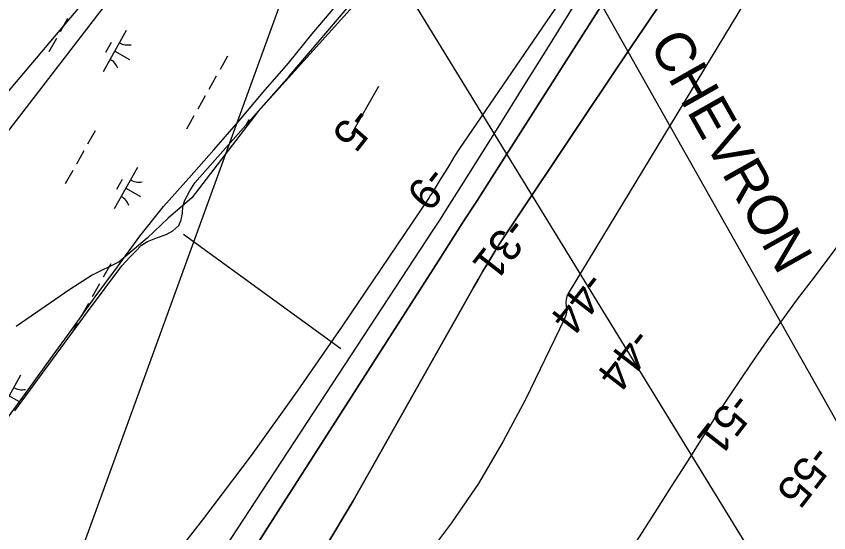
# Model space of a CAD drawing. Extents: x 3913936 to 3933962, y 195330 to 217741.
# Drawn here: x 3922950 to 3923806, y 202729 to 203273 of the extents above; entities that cross this region are included whole.
import ezdxf

# ---------------------------------------------------------------- set-up
doc = ezdxf.new("R2010")
doc.units = 0
for name, color, linetype in [('V-ANNO-TEXT', 7, 'Continuous'), ('V-LEVE-TOET', 7, 'Continuous'), ('V-RIVR-EDGE', 7, 'Continuous'), ('V-RIVR-RANG', 7, 'Continuous'), ('V-RRAP-FSHR', 7, 'Continuous'), ('V-TOPO-DPTH', 7, 'Continuous'), ('V-TOPO-MAJR', 7, 'Continuous'), ('V-TOPO-MINR', 7, 'Continuous'), ('V-UTIL-IDEN', 7, 'Continuous'), ('V-UTIL-LINE', 7, 'Continuous'), ('V-WETL-SWMP', 7, 'Continuous')]:
    doc.layers.add(name, color=color, linetype=linetype)

msp = doc.modelspace()

# ---------------------------------------------------------------- linework, layer by layer
at = {"layer": 'V-ANNO-TEXT'}
msp.add_lwpolyline([(3923713.15, 204620.63), (3922595.25, 201547.11)], dxfattribs=at)
at = {"layer": 'V-LEVE-TOET'}
msp.add_line((3923126.26, 203043.7), (3923292.08, 202923.2), dxfattribs=at)
at = {"layer": 'V-RIVR-EDGE'}
msp.add_lwpolyline([(3923321.17, 203302.44), (3923204.48, 203172.78), (3923134.93, 203082.02), (3923110.18, 203060.8), (3923087.78, 203039.58), (3923058.32, 203014.83), (3923030.03, 203000.69), (3923006.45, 202985.36), (3922949.87, 202946.46)], dxfattribs=at)
at = {"layer": 'V-RRAP-FSHR'}
msp.add_lwpolyline([(3922939.13, 202847.62), (3922962.63, 202879.98), (3922986.14, 202912.35), (3923009.65, 202944.71), (3923033.16, 202977.72), (3923056.66, 203009.43), (3923080.17, 203041.8), (3923105.14, 203072.99), (3923131.68, 203102.91), (3923158.23, 203132.83), (3923184.52, 203162.97), (3923210.3, 203193.56), (3923236.77, 203224.14), (3923261.86, 203254.73), (3923287.64, 203285.31)], dxfattribs=at)
at = {"layer": 'V-TOPO-DPTH'}
for points in [[(3924399.57, 204415.69), (3923953.85, 203655.86), (3923952.77, 203654.08), (3923950.87, 203651.18), (3923886.24, 203555.82), (3923853.92, 203507.32), (3923822.1, 203458.5), (3923791.04, 203409.19), (3923760.48, 203359.56), (3923531.63, 202981.34), (3923530.2, 202978.21), (3923529.27, 202974.99), (3923529.1, 202971.64), (3923529.42, 202968.21), (3923529.81, 202964.75), (3923529.74, 202961.35), (3923528.99, 202958.03), (3923527.8, 202954.76), (3923486.42, 202869.69), (3923462.69, 202824.86), (3923437.03, 202781.27), (3923408.46, 202739.52), (3923377.96, 202699)], [(3924399.57, 204415.69), (3923953.85, 203655.86), (3923952.77, 203654.08), (3923950.87, 203651.18), (3923886.24, 203555.82), (3923853.92, 203507.32), (3923822.1, 203458.5), (3923791.04, 203409.19), (3923760.48, 203359.56), (3923531.63, 202981.34), (3923530.2, 202978.21), (3923529.27, 202974.99), (3923529.1, 202971.64), (3923529.42, 202968.21), (3923529.81, 202964.75), (3923529.74, 202961.35), (3923528.99, 202958.03), (3923527.8, 202954.76), (3923486.42, 202869.69), (3923462.69, 202824.86), (3923437.03, 202781.27), (3923408.46, 202739.52), (3923377.96, 202699)], [(3923857.86, 203782.03), (3923855.37, 203777.58), (3923834.62, 203742.37), (3923834.22, 203741.94), (3923833.77, 203741.64), (3923832.65, 203741.59), (3923416.84, 203134.08), (3923411.85, 203125.86), (3923406.85, 203117.65), (3923401.82, 203109.45), (3923396.77, 203101.27), (3923389.59, 203089.64), (3923388.11, 203087.28), (3923386.62, 203084.94), (3923385.09, 203082.61), (3923383.55, 203080.3), (3923293.38, 202946.75), (3923245.92, 202878.27), (3923197.37, 202810.59), (3923147.19, 202744.12), (3923095.91, 202678.46), (3922791.11, 202297.8)], [(3922202.27, 201498.77), (3922970.95, 202357.51), (3923063.96, 202493.59), (3923089.04, 202534.05), (3923130.72, 202600.96), (3923172.59, 202667.75), (3923214.77, 202734.34), (3923257.14, 202800.82), (3923394.77, 203015.67), (3923408.23, 203036.69), (3923421.68, 203057.72), (3923435.11, 203078.75), (3923448.54, 203099.79), (3923524.43, 203218.78), (3923575.77, 203299.34), (3923627.08, 203379.91), (3923678.32, 203460.53), (3923729.53, 203541.17), (3923871.35, 203718.33), (3923873.24, 203720.48), (3923889.48, 203748.05)], [(3922202.27, 201498.77), (3922970.95, 202357.51), (3923063.96, 202493.59), (3923089.04, 202534.05), (3923130.72, 202600.96), (3923172.59, 202667.75), (3923214.77, 202734.34), (3923257.14, 202800.82), (3923394.77, 203015.67), (3923408.23, 203036.69), (3923421.68, 203057.72), (3923435.11, 203078.75), (3923448.54, 203099.79), (3923524.43, 203218.78), (3923575.77, 203299.34), (3923627.08, 203379.91), (3923678.32, 203460.53), (3923729.53, 203541.17), (3923871.35, 203718.33), (3923873.24, 203720.48), (3923889.48, 203748.05), (3923909.75, 203692.04)], [(3923909.75, 203692.04), (3923908.53, 203689.99), (3923907.28, 203687.96), (3923904.67, 203683.97), (3923901.98, 203680.03), (3923900.63, 203678.06), (3923899.26, 203676.11), (3923741.31, 203450.39), (3923693.08, 203380.95), (3923645.18, 203311.28), (3923597.79, 203241.27), (3923550.72, 203171.04), (3923460, 203034.62), (3923458.56, 203032.41), (3923457.13, 203030.2), (3923455.73, 203027.96), (3923454.35, 203025.72), (3923446.77, 203013.22), (3923441.66, 203004.69), (3923436.6, 202996.14), (3923431.62, 202987.53), (3923426.69, 202978.9), (3923304.88, 202762.93), (3923245.38, 202663.04)], [(3923245.38, 202663.04), (3923304.88, 202762.93), (3923426.69, 202978.9), (3923431.62, 202987.53), (3923436.6, 202996.14), (3923441.66, 203004.69), (3923446.77, 203013.22), (3923454.35, 203025.72), (3923455.73, 203027.96), (3923457.13, 203030.2), (3923458.56, 203032.41), (3923460, 203034.62), (3923550.72, 203171.04), (3923597.79, 203241.27), (3923645.18, 203311.28), (3923693.08, 203380.95), (3923741.31, 203450.39), (3923899.26, 203676.11)]]:
    msp.add_lwpolyline(points, dxfattribs=at)
at = {"layer": 'V-TOPO-MAJR'}
msp.add_lwpolyline([(3923814.5, 203030.35), (3923790.54, 202998.64), (3923772.87, 202975.25), (3923757.93, 202955.1), (3923743.22, 202934.79), (3923728.85, 202914.23), (3923714.72, 202893.51), (3923687.34, 202852.63), (3923685.77, 202850.17), (3923685.52, 202849.75), (3923685.26, 202849.34), (3923655.33, 202802.01), (3923640.07, 202777.95), (3923624.77, 202753.92), (3923609.4, 202729.94), (3923593.98, 202705.98)], dxfattribs=at)
at = {"layer": 'V-TOPO-MINR'}
for points in [[(3924399.57, 204415.69), (3923953.85, 203655.86), (3923952.77, 203654.08), (3923950.87, 203651.18), (3923886.24, 203555.82), (3923853.92, 203507.32), (3923822.1, 203458.5), (3923791.04, 203409.19), (3923760.48, 203359.56), (3923531.63, 202981.34), (3923530.2, 202978.21), (3923529.27, 202974.99), (3923529.1, 202971.64), (3923529.42, 202968.21), (3923529.81, 202964.75), (3923529.74, 202961.35), (3923528.99, 202958.03), (3923527.8, 202954.76), (3923486.42, 202869.69), (3923462.69, 202824.86), (3923437.03, 202781.27), (3923408.46, 202739.52), (3923377.96, 202699)], [(3923857.86, 203782.03), (3923855.37, 203777.58), (3923834.62, 203742.37), (3923834.22, 203741.94), (3923833.77, 203741.64), (3923832.65, 203741.59), (3923416.84, 203134.08), (3923411.85, 203125.86), (3923406.85, 203117.65), (3923401.82, 203109.45), (3923396.77, 203101.27), (3923389.59, 203089.64), (3923388.11, 203087.28), (3923386.62, 203084.94), (3923385.09, 203082.61), (3923383.55, 203080.3), (3923293.38, 202946.75), (3923245.92, 202878.27), (3923197.37, 202810.59), (3923147.19, 202744.12), (3923095.91, 202678.46), (3922791.11, 202297.8)], [(3923873.73, 203765.03), (3923854.12, 203731.76), (3923563.2, 203326.14), (3923536.82, 203283.59), (3923510.39, 203241.07), (3923483.89, 203198.6), (3923457.33, 203156.16), (3923418.86, 203094.8), (3923411.47, 203083.09), (3923404.03, 203071.41), (3923396.52, 203059.77), (3923388.97, 203048.17), (3923043.25, 202520.53), (3923021.49, 202487.23), (3922999.8, 202453.88), (3922978.21, 202420.46), (3922956.69, 202387.01), (3922940, 202360.98)], [(3923889.48, 203748.05), (3923873.24, 203720.48), (3923871.35, 203718.33), (3923729.53, 203541.17), (3923678.32, 203460.53), (3923627.08, 203379.91), (3923575.77, 203299.34), (3923524.43, 203218.78), (3923448.54, 203099.79), (3923435.11, 203078.75), (3923421.68, 203057.72), (3923408.23, 203036.69), (3923394.77, 203015.67), (3923257.14, 202800.82), (3923214.77, 202734.34), (3923172.59, 202667.75), (3923130.72, 202600.96), (3923089.04, 202534.05), (3923063.96, 202493.59), (3922970.95, 202357.51), (3922202.27, 201498.77)], [(3923899.26, 203676.11), (3923741.31, 203450.39), (3923693.08, 203380.95), (3923645.18, 203311.28), (3923597.79, 203241.27), (3923550.72, 203171.04), (3923460, 203034.62), (3923458.56, 203032.41), (3923457.13, 203030.2), (3923455.73, 203027.96), (3923454.35, 203025.72), (3923446.77, 203013.22), (3923441.66, 203004.69), (3923436.6, 202996.14), (3923431.62, 202987.53), (3923426.69, 202978.9), (3923304.88, 202762.93), (3923245.38, 202663.04)], [(3923331.56, 203199.52), (3923303.3, 203149.66)]]:
    msp.add_lwpolyline(points, dxfattribs=at)
at = {"layer": 'V-UTIL-LINE'}
for points in [[(3928315.82, 212388.13), (3926944.7, 210748.94), (3926592.74, 210251.47), (3926408.93, 209914.99), (3925628.64, 208474.44), (3925139.98, 207727.42), (3924555.96, 206253.65), (3924055.82, 204771.45), (3923484.9, 203858.52), (3922256.01, 202262.65), (3921816.4, 201905.57), (3920704.84, 200345.08), (3920462.44, 200062.72)], [(3928328.32, 212380.93), (3926784.14, 210502.92), (3926424.72, 209908.68), (3925640.45, 208467.64), (3924952.2, 207329.25), (3923971.74, 204752.16), (3923252.9, 203563.68), (3921560.17, 201558.84), (3920397.87, 200112.86)], [(3926953.75, 204871.69), (3926114.53, 203439.18), (3924358.1, 201675.2), (3923230.85, 203513.49)], [(3924378.52, 201846.64), (3923455.57, 203482.72), (3923464.33, 203499.92)]]:
    msp.add_lwpolyline(points, dxfattribs=at)
at = {"layer": 'V-WETL-SWMP'}
for p, q in [((3923237.65, 203210.33), (3923298.69, 203281.78)), ((3923004.02, 203270.93), (3922996.18, 203256.98)), ((3923065.94, 203258.57), (3923041.44, 203214.99)), ((3922992.26, 203250.01), (3922984.41, 203236.06)), ((3923049.91, 203245.79), (3923044.03, 203235.33)), ((3923053.69, 203236.78), (3923069.38, 203227.96)), ((3923172.53, 203231.26), (3923164.69, 203217.31)), ((3923138.13, 203097.88), (3923237.65, 203210.33)), ((3923160.77, 203210.34), (3923152.93, 203196.39)), ((3923149.01, 203189.42), (3923141.17, 203175.47)), ((3923137.25, 203168.5), (3923129.41, 203154.55)), ((3923194.9, 203164.28), (3923191.43, 203158.11)), ((3923033, 203152.59), (3923025.16, 203138.64)), ((3923021.24, 203131.67), (3923013.4, 203117.72)), ((3923009.48, 203110.75), (3923001.63, 203096.8)), ((3923077.57, 203114.1), (3923053.07, 203070.52)), ((3923061.54, 203101.32), (3923055.66, 203090.86)), ((3923065.32, 203092.31), (3923081.01, 203083.49)), ((3923132.75, 203089.37), (3923138.13, 203097.88)), ((3923127.63, 203079.58), (3923132.75, 203089.37)), ((3923125.59, 203072.88), (3923127.63, 203079.58)), ((3923123.83, 203058.98), (3923125.1, 203065.93)), ((3923125.1, 203065.93), (3923125.59, 203072.88)), ((3923121.27, 203052.8), (3923123.83, 203058.98)), ((3923115.12, 203047.38), (3923121.27, 203052.8)), ((3923088.39, 203035.99), (3923098.93, 203040.39)), ((3923098.93, 203040.39), (3923107.92, 203043.5)), ((3923107.92, 203043.5), (3923115.12, 203047.38)), ((3923075.55, 203025.4), (3923081.97, 203032.11)), ((3923081.97, 203032.11), (3923088.39, 203035.99)), ((3923069.65, 203019.72), (3923075.55, 203025.4)), ((3923061.19, 203010.44), (3923069.65, 203019.72)), ((3923025.04, 202961.96), (3923061.19, 203010.44)), ((3923049.56, 203012.5), (3923041.72, 202998.55)), ((3923037.8, 202991.58), (3923029.96, 202977.63)), ((3923026.04, 202970.66), (3923018.2, 202956.71)), ((3922948.4, 202857.8), (3923025.04, 202961.96)), ((3923014.28, 202949.74), (3923008.56, 202939.57)), ((3922954.6, 202895.35), (3922930.1, 202851.76)), ((3922942.35, 202873.55), (3922954.83, 202866.54))]:
    msp.add_line(p, q, dxfattribs=at)
for centre, start, end in [((3923067.43, 203260.74), 239.88608, 281.42974), ((3923040.36, 203212.59), 19.88608, 61.42973), ((3923079.06, 203116.27), 239.88608, 281.42974), ((3923051.99, 203068.12), 19.88608, 61.42973), ((3922956.09, 202897.51), 239.88608, 281.42974)]:
    msp.add_arc(centre, 17.62, start, end, dxfattribs=at)

# ---------------------------------------------------------------- texts
at = {"layer": 'V-RIVR-RANG'}
for s, rotation, p in [('-5', 232.02833, (3923305.75, 203180.03)), ('-9', 232.02833, (3923384.16, 203117.97)), ('-31', 232.02833, (3923468.98, 203064.12)), ('-44', 232.1655, (3923550.95, 203006.75)), ('-44', 232.1655, (3923600.06, 202947.17)), ('-51', 232.1655, (3923705.35, 202879.49)), ('-55', 232.1655, (3923789.1, 202824.3))]:
    msp.add_text(s, height=33.5, rotation=rotation, dxfattribs=at).set_placement(p)
at = {"layer": 'V-UTIL-IDEN'}
msp.add_text('CHEVRON', height=42, rotation=299.4284, dxfattribs=at).set_placement((3923616.13, 203243.99))

doc.saveas('drawing.dxf')
